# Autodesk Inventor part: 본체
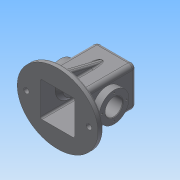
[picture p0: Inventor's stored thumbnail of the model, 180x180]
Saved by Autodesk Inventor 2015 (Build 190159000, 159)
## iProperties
Created: 2017-07
Part Number: 본체
Material: 일반
Document SubType Name: Modeling
Designer: owner
Density: 1 g/cm^3
Appearance: 기본값
Author: owner
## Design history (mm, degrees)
sketch "스케치1"
  geometry: L1 (37, -55)-(-37, -55); L2 (-37, -55)-(-37, 55); L3 (-37, 55)-(37, 55); L4 (37, 55)-(37, -55); L5 (37, -55)-(-37, 55); L6 (-37, -55)-(37, 55); 1 further point
  constraints: 12 end point, 2 midpoint, 2 parallel, 1 horizontal, 1 perpendicular
  dimensions: "d0" = 74 distance of L2.end L3.end; "d1" = 110 distance of L3.end L1.start
extrude "돌출1" new body sketch "스케치1" stored distance "d2" = 74; taper "d3" = 0 deg
fillet "모깎기1" dims "d4" = 8
feature "쉘1" dims "d5" = 5
sketch "스케치2" dims "d6" = 65, "d7" = 75
  geometry: L1 (-8, 66)-(-8, 8) reference; L2 (58, 0)-(0, 0) reference; L3 (66, 8)-(66, 66) reference; L4 (0, 74)-(58, 74) reference; A1 r 8 centre (0, 66) between (0, 74) and (-8, 66) reference; A2 r 8 centre (0, 8) between (-8, 8) and (0, 0) reference; A3 r 8 centre (58, 8) between (58, 0) and (66, 8) reference; A4 r 8 centre (58, 66) between (66, 66) and (58, 74) reference; 2 further points; 1 other entity
  constraints: 1 coincident, 2 other
extrude "돌출2" join sketch "스케치2" distance "d8" = 10; taper "d9" = 0 deg
sketch "스케치4"
  geometry: C1 r 27.5 at (29, -47); 1 further point
  constraints: 1 centre point, 1 coincident
  dimensions: "d10" = 55 diameter of C1
extrude "돌출3" join sketch "스케치4" distance "d11" = 13; taper "d12" = 0 deg
sketch "스케치5"
  geometry: C1 r 27.5 at (29, -47); 1 further point
  constraints: 1 centre point, 1 coincident
  dimensions: "d13" = 55 diameter of C1
extrude "돌출4" join sketch "스케치5" distance "d14" = 13; taper "d15" = 0 deg
sketch "스케치7"
  geometry: L1 (-50, 27.5)-(-50, -27.5) reference; L2 (-32, 0)-(-25, 0); L3 (-32, -55)-(-32, 47) reference; L4 (-32, 27.5)-(-25, 20.5); L5 (-25, 20.5)-(-25, 0); L6 (-32, 27.5)-(-32, 0); L7 (32, 47)-(32, -55) reference; 1 further point
  constraints: 8 end point, 2 point on line, 1 horizontal, 1 horizontal alignment, 1 perpendicular
  dimensions: "d16" = 7 distance between parallel lines of L3 L5; "d17" = 135 deg angle of L3 L4; "d91" = 55 diameter of L4.start L2
revolve "회전1" sketch "스케치7" stored, may be unused: angle "d19" = 90 deg
hole "구멍1" diameter "d22" = 32; stored, may be unused: countersink angle "d26" = 90 deg, drill point angle "d28" = 0 deg; dims "d20" = 10, "d21" = 10, "d23" = 6, "d24" = 4, "d25" = 2, "d27" = 8
sketch "스케치8"
  geometry: C1 r 16 at (0, 0) reference; 1 further point
  constraints: 1 vertical alignment
  dimensions: "d29" = 22.5 distance of point (0, 22.5) C1.centre
hole "구멍2" sketch "스케치8" at (0, 22.5) diameter "d30" = 3.242; stored, may be unused: countersink angle "d34" = 90 deg, drill point angle "d36" = 118 deg; dims "d31" = 8, "d32" = 4, "d33" = 2, "d35" = 10
node "작업 평면2"
  node "작업 평면1"
sketch "스케치9"
  geometry: L1 (-1.5, -9)-(38.5, -9); L2 (38.5, -9)-(38.5, -49); L3 (38.5, -49)-(-1.5, -49); L4 (-1.5, -49)-(-1.5, -9); L5 (-1.5, -9)-(38.5, -49); L6 (38.5, -9)-(-1.5, -49); 1 further point
  constraints: 12 end point, 2 midpoint, 2 parallel, 2 perpendicular, 1 horizontal
  dimensions: "d41" = 40 distance of L2.end L3.end
extrude "돌출5" join sketch "스케치9" stored distance "d42" = 13; taper "d43" = 5 deg
sketch "스케치10"
  geometry: 2 further points
  constraints: 1 coincident
hole "구멍3" sketch "스케치10" at (-18.5, 29) diameter "d44" = 21; stored, may be unused: countersink angle "d48" = 90 deg, drill point angle "d50" = 0 deg; dims "d45" = 8, "d46" = 28, "d47" = 4, "d49" = 10
sketch "스케치12"
  geometry: L1 (47, -37)-(-45, -37) reference; L2 (-45, -65)-(-45, 65) reference; L3 (27.194, -37)-(-45, -55); L4 (-45, -65)-(-45, 65) reference; L5 (-55, -65)-(-55, 65) reference; L6 (50, -29)-(50, -10.5) reference; L7 (50, -10.5)-(61, -10.5) reference; L8 (61, -10.5)-(61, -14) reference; L9 (61, -14)-(65, -14) reference; L10 (65, -14)-(65, -20) reference; L11 (65, -20)-(55, -20.875) reference; L12 (55, -20.875)-(55, -29) reference; L13 (47, -37)-(-45, -37) reference; L14 (-45, -37)-(-45, -65) reference; L15 (-45, -65)-(-55, -65) reference; L16 (-55, -65)-(-55, -32) reference; L17 (-55, -32)-(47, -32) reference; L18 (55, 29)-(55, 20.875) reference; L19 (55, 20.875)-(65, 20) reference; L20 (65, 20)-(65, 14) reference; L21 (65, 14)-(61, 14) reference; L22 (61, 14)-(61, 10.5) reference; L23 (61, 10.5)-(50, 10.5) reference; L24 (50, 10.5)-(50, 29) reference; L25 (47, 32)-(-55, 32) reference; L26 (-55, 32)-(-55, 65) reference; L27 (-55, 65)-(-45, 65) reference; L28 (-45, 65)-(-45, 37) reference; L29 (-45, 37)-(47, 37) reference; L30 (27.194, 37)-(-45, 55); A1 r 3 centre (47, -29) between (47, -32) and (50, -29) reference; A2 r 8 centre (47, -29) between (47, -37) and (55, -29) reference; A3 r 8 centre (47, 29) between (55, 29) and (47, 37) reference; A4 r 3 centre (47, 29) between (50, 29) and (47, 32) reference; 1 further point
  constraints: 4 end point, 4 point on line
  dimensions: "d52" = 14 deg angle of L3 L15; "d53" = 10 distance from line of L3.end L15; "d54" = 10 distance from line of L30.end L27; "d55" = 14 deg angle of L27 L30
  node "투영된 루프1"
  node "절단 모서리 투영1"
feature "리브2" dims "d62" = 1, "d63" = 10, "d64" = 0, "d65" = 0, "d66" = 1, "d67" = 1
chamfer "모따기1" distance "d69" = 1; stored, may be unused: second distance "d70" = 2, angle "d71" = 45 deg
fillet "모깎기3" dims "d72" = 0.5
fillet "모깎기4" dims "d73" = 0.5
sketch "스케치13"
  geometry: C1 r 5 at (-29, -37); C2 r 5 at (87, -37); 1 further point; 1 other entity
  constraints: 2 centre point, 2 horizontal alignment, 1 other
  dimensions: "d74" = 10 diameter of C1; "d75" = 10 diameter of C2; "d76" = 58 distance of C1.centre point (29, -37); "d77" = 116 distance of C2.centre C1.centre
extrude "돌출6" cut sketch "스케치13" taper "d9" = 0 deg; stored distance "d78" = 13; taper "d79" = 0 deg
fillet "모깎기5" dims "d80" = 3
fillet "모깎기6" dims "d81" = 3
fillet "모깎기7" dims "d82" = 3
fillet "모깎기9" dims "d84" = 3
fillet "모깎기10" dims "d85" = 3
fillet "모깎기11" dims "d86" = 3
sketch "스케치14"
  geometry: L1 (46.011, 18)-(11.989, 18) reference; L2 (66, -89)-(66, 0) reference; 1 further point
  constraints: 1 other
  dimensions: "d87" = 30 distance from line of L1 point (29, -12); "d88" = 37 distance from line of point (29, -12) L2
feature "엠보싱1" sketch "스케치14" dims "d89" = 0.5, "d90" = 0
feature "리브3" dims "d92" = 1, "d93" = 10, "d94" = 0, "d95" = 0, "d96" = 1, "d97" = 1
fillet "모깎기12" dims "d98" = 2
fillet "모깎기13" dims "d99" = 2
node "솔리드1"
mirror "대칭1"
pattern_circular "원형 패턴1" dims angle "d38" = 360 deg
mirror "대칭2"
